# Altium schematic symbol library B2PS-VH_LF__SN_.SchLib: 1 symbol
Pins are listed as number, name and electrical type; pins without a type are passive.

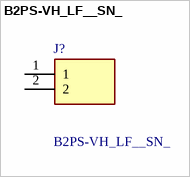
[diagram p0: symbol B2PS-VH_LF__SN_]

## B2PS-VH_LF__SN_
designator J?
WIRE-BOARD CONNECTOR, HEADER 2 POSITION 3.96MM; Connector Systems:Wire-to-Board; Pitch Spacing:3.96mm; No. of Rows:1Rows; No. of Contacts:2Contacts; Contact Termination Type:Through Hole; Product Range:VH Series; Gender:Header RoHS Compliant: Yes; Manufacturer_Name: JST (JAPAN SOLDERLESS TERMINALS); Manufacturer_Part_Number: B2PS-VH(LF)(SN); Geometry.Height: 8.5mm
footprint B2PSVHLFSN
pins: 1, 2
